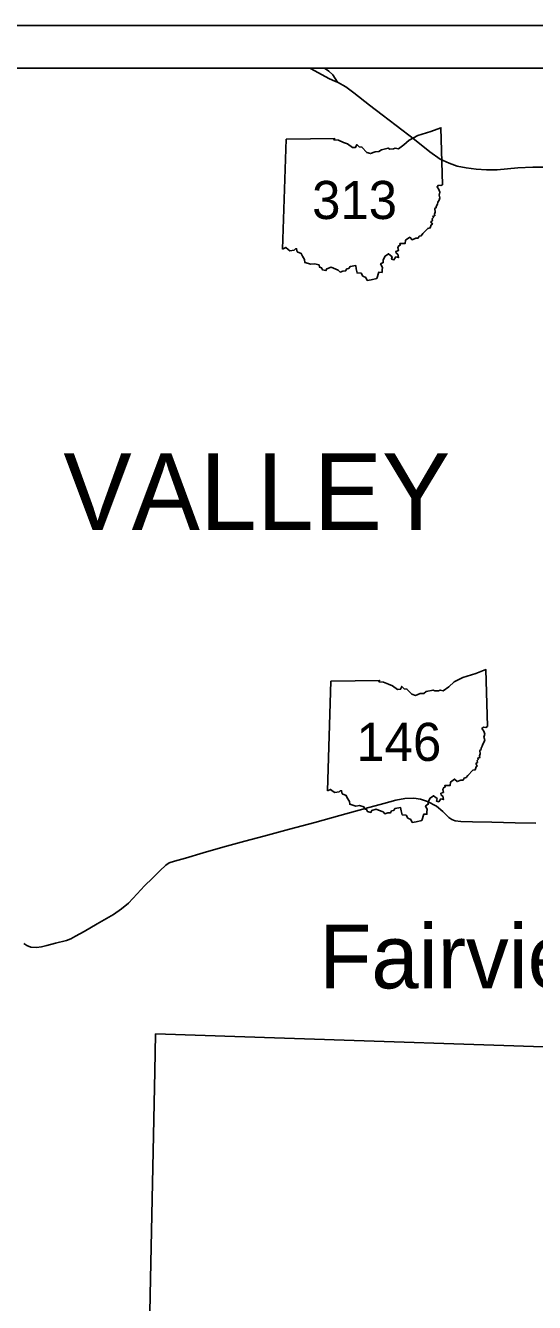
# Model space of a CAD drawing. Extents: x -452339 to 6403467, y -1 to 1814750.
# Drawn here: x -379658 to -373672, y 1646851 to 1661857 of the extents above; entities that cross this region are included whole.
import ezdxf

# ---------------------------------------------------------------- set-up
doc = ezdxf.new("R2010")
doc.units = 0
for name, color, linetype in [('Default', 7, 'Continuous'), ('GM_X_Adjacent_County_Text', 7, 'Continuous'), ('GM_X_County_Road', 7, 'Continuous'), ('GM_X_County_ROW', 7, 'Continuous'), ('GM_X_Section_Text', 7, 'Continuous'), ('GM_X_Township_Subdivision_Text', 7, 'Continuous')]:
    doc.layers.add(name, color=color, linetype=linetype)

msp = doc.modelspace()

# ---------------------------------------------------------------- linework, layer by layer
at = {"layer": 'Default'}
for p, q in [((-403040, 1661357), (-345663, 1661357)), ((-376635, 1659229), (-376594, 1660521)), ((-376107, 1652862), (-376065, 1654153))]:
    msp.add_line(p, q, dxfattribs=at)
msp.add_lwpolyline([(-403540, 1661857), (-345163, 1661857), (-345163, 1603479), (-403540, 1603479)], close=True, dxfattribs=at)
for points in [[(-376594, 1660521), (-376021, 1660529), (-376030, 1660513), (-375976, 1660510), (-375919, 1660482), (-375870, 1660465), (-375811, 1660424), (-375776, 1660425), (-375760, 1660458), (-375733, 1660432), (-375701, 1660428), (-375645, 1660366), (-375599, 1660352), (-375544, 1660374), (-375503, 1660377), (-375472, 1660398), (-375394, 1660416), (-375372, 1660405), (-375330, 1660408), (-375309, 1660415), (-375273, 1660408), (-375210, 1660455), (-375144, 1660510), (-375042, 1660563), (-374892, 1660612), (-374772, 1660656), (-374755, 1659986)], [(-374755, 1659986), (-374772, 1659977), (-374800, 1659981), (-374818, 1659963), (-374795, 1659931), (-374785, 1659898), (-374794, 1659862), (-374785, 1659832), (-374791, 1659806), (-374808, 1659781), (-374814, 1659757), (-374829, 1659732), (-374828, 1659718), (-374842, 1659707), (-374839, 1659665), (-374846, 1659642), (-374844, 1659622), (-374867, 1659617), (-374861, 1659600), (-374876, 1659587), (-374873, 1659565), (-374889, 1659551), (-374873, 1659523), (-374886, 1659514), (-374897, 1659480), (-374926, 1659473), (-374984, 1659411), (-375004, 1659387), (-375027, 1659381), (-375040, 1659357), (-375068, 1659357), (-375112, 1659340), (-375139, 1659369), (-375188, 1659334), (-375194, 1659294), (-375255, 1659295), (-375253, 1659274), (-375267, 1659269), (-375279, 1659248), (-375272, 1659212), (-375301, 1659203), (-375297, 1659182), (-375279, 1659169), (-375270, 1659129), (-375301, 1659137), (-375326, 1659103), (-375352, 1659111), (-375344, 1659140), (-375387, 1659174), (-375428, 1659147), (-375450, 1659102), (-375450, 1659072), (-375481, 1659055), (-375461, 1659013), (-375465, 1658984), (-375464, 1658956), (-375503, 1658957), (-375526, 1658883)], [(-375526, 1658883), (-375593, 1658869), (-375639, 1658861), (-375655, 1658894), (-375689, 1658912), (-375710, 1658946), (-375758, 1658950), (-375769, 1658997), (-375774, 1659035), (-375840, 1659025), (-375857, 1659002), (-375880, 1658996), (-375894, 1658973), (-375925, 1658971), (-375959, 1658960), (-375981, 1658982), (-376037, 1659006), (-376062, 1659017), (-376114, 1658999), (-376125, 1658977), (-376166, 1658987), (-376176, 1659011), (-376201, 1659019), (-376206, 1659044), (-376260, 1659058), (-376301, 1659052), (-376373, 1659073), (-376378, 1659107), (-376402, 1659148), (-376415, 1659177), (-376461, 1659198), (-376470, 1659233), (-376484, 1659232), (-376498, 1659218), (-376549, 1659211), (-376569, 1659225), (-376597, 1659249), (-376635, 1659229)], [(-376065, 1654153), (-375493, 1654161), (-375501, 1654145), (-375448, 1654142), (-375390, 1654115), (-375342, 1654097), (-375282, 1654056), (-375247, 1654057), (-375232, 1654091), (-375205, 1654064), (-375172, 1654060), (-375116, 1653998), (-375070, 1653985), (-375015, 1654006), (-374974, 1654009), (-374944, 1654030), (-374865, 1654048), (-374843, 1654037), (-374802, 1654040), (-374781, 1654047), (-374744, 1654040), (-374681, 1654087), (-374615, 1654143), (-374514, 1654195), (-374363, 1654244), (-374243, 1654289), (-374226, 1653618)], [(-374226, 1653618), (-374244, 1653609), (-374271, 1653613), (-374290, 1653595), (-374267, 1653564), (-374256, 1653530), (-374266, 1653494), (-374256, 1653464), (-374262, 1653438), (-374280, 1653413), (-374286, 1653390), (-374300, 1653364), (-374299, 1653350), (-374313, 1653339), (-374311, 1653297), (-374318, 1653274), (-374315, 1653254), (-374338, 1653249), (-374333, 1653232), (-374347, 1653219), (-374344, 1653197), (-374361, 1653183), (-374345, 1653155), (-374357, 1653146), (-374368, 1653112), (-374397, 1653105), (-374455, 1653043), (-374476, 1653019), (-374499, 1653013), (-374512, 1652989), (-374540, 1652989), (-374583, 1652972), (-374611, 1653001), (-374659, 1652966), (-374665, 1652926), (-374726, 1652927), (-374724, 1652907), (-374738, 1652901), (-374750, 1652880), (-374743, 1652844), (-374772, 1652835), (-374769, 1652814), (-374750, 1652801), (-374742, 1652761), (-374772, 1652769), (-374797, 1652735), (-374823, 1652743), (-374815, 1652772), (-374859, 1652806), (-374900, 1652779), (-374921, 1652734), (-374922, 1652705), (-374953, 1652687), (-374933, 1652645), (-374936, 1652616), (-374936, 1652588), (-374974, 1652589), (-374998, 1652515)], [(-374998, 1652515), (-375064, 1652501), (-375110, 1652493), (-375127, 1652526), (-375160, 1652544), (-375182, 1652578), (-375229, 1652582), (-375241, 1652629), (-375246, 1652667), (-375311, 1652657), (-375329, 1652634), (-375352, 1652628), (-375365, 1652605), (-375397, 1652603), (-375431, 1652592), (-375453, 1652615), (-375508, 1652638), (-375533, 1652649), (-375585, 1652631), (-375596, 1652609), (-375637, 1652619), (-375647, 1652643), (-375672, 1652651), (-375678, 1652676), (-375731, 1652690), (-375772, 1652684), (-375845, 1652705), (-375849, 1652739), (-375874, 1652780), (-375886, 1652809), (-375932, 1652830), (-375941, 1652865), (-375956, 1652864), (-375969, 1652850), (-376020, 1652843), (-376040, 1652857), (-376069, 1652881), (-376107, 1652862)]]:
    msp.add_lwpolyline(points, dxfattribs=at)
at = {"layer": 'GM_X_County_Road'}
for points in [[(-376312, 1661357), (-376254, 1661325), (-376091, 1661236), (-376013, 1661198), (-375988, 1661193), (-375890, 1661136), (-375796, 1661067), (-375611, 1660920), (-375464, 1660808), (-375297, 1660681), (-375084, 1660517), (-374904, 1660373), (-374780, 1660288), (-374675, 1660240), (-374580, 1660206), (-374475, 1660184), (-374356, 1660169), (-374235, 1660161), (-374110, 1660163), (-373867, 1660184), (-373693, 1660193), (-373540, 1660191)], [(-379678, 1651070), (-379642, 1651046), (-379597, 1651027), (-379529, 1651022), (-379471, 1651030), (-379406, 1651047), (-379304, 1651075), (-379174, 1651104), (-379124, 1651125), (-379069, 1651155), (-378967, 1651211), (-378816, 1651299), (-378622, 1651411), (-378528, 1651476), (-378447, 1651545), (-378343, 1651653), (-378258, 1651748), (-378165, 1651839), (-378078, 1651925), (-378006, 1651990), (-377967, 1652016), (-377907, 1652037), (-377777, 1652074), (-377570, 1652135), (-377339, 1652200), (-377078, 1652271), (-376854, 1652332), (-376555, 1652412), (-376256, 1652491), (-375961, 1652573), (-375662, 1652655), (-375442, 1652713), (-375301, 1652755), (-375195, 1652774), (-375091, 1652778), (-375011, 1652767), (-374930, 1652737), (-374826, 1652683), (-374749, 1652619), (-374680, 1652550), (-374644, 1652525), (-374603, 1652509), (-374539, 1652502), (-374399, 1652499), (-374173, 1652496), (-373901, 1652489), (-373657, 1652482)]]:
    msp.add_lwpolyline(points, dxfattribs=at)
at = {"layer": 'GM_X_County_ROW'}
msp.add_lwpolyline([(-375988, 1661193), (-376042, 1661277), (-376090, 1661319), (-376143, 1661357)], dxfattribs=at)
at = {"layer": 'GM_X_Section_Text'}
for p, q in [((-378129, 1650007), (-378138, 1649564)), ((-376612, 1649956), (-378129, 1650007)), ((-371621, 1649789), (-376612, 1649956)), ((-378138, 1649564), (-378192, 1646942)), ((-378192, 1646942), (-378219, 1645641))]:
    msp.add_line(p, q, dxfattribs=at)

# ---------------------------------------------------------------- texts
at = {"layer": 'Default'}
for s, p in [('313', (-376287, 1659583)), ('146', (-375767, 1653215))]:
    msp.add_text(s, height=447.7, dxfattribs=at).set_placement(p)
at = {"layer": 'GM_X_Adjacent_County_Text'}
msp.add_text('Fairview', height=750, rotation=0, dxfattribs=at).set_placement((-376204, 1650542))
at = {"layer": 'GM_X_Township_Subdivision_Text'}
msp.add_text('VALLEY', height=900, rotation=0, dxfattribs=at).set_placement((-379212, 1655928))

doc.saveas('drawing.dxf')
